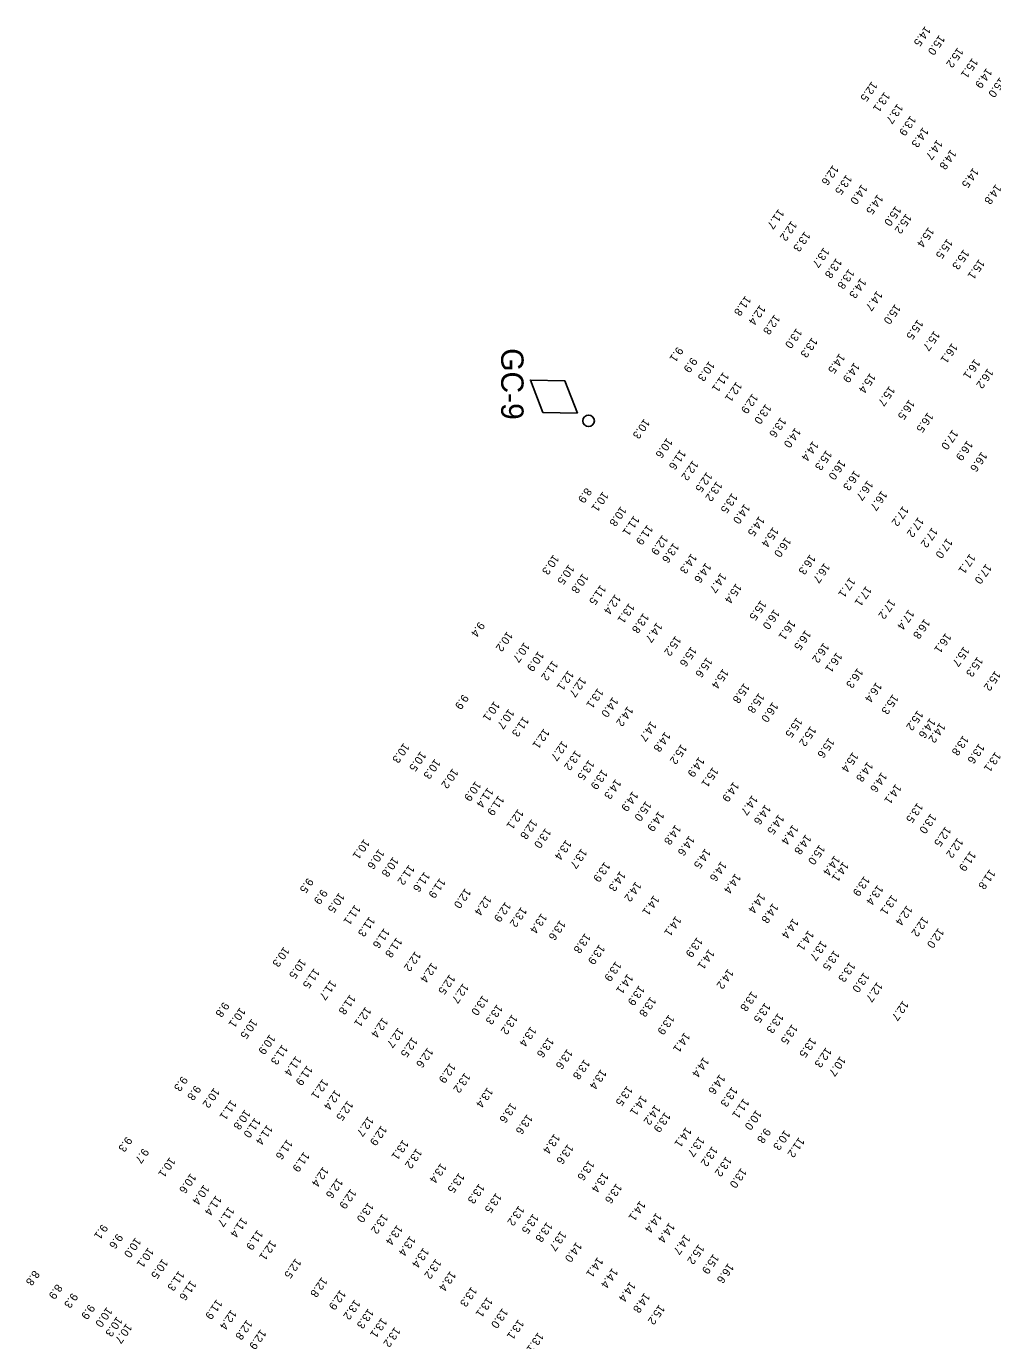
# Model space of a CAD drawing. Extents: x 815385 to 820851, y 582449 to 604245.
# Drawn here: x 817976 to 818580, y 586286 to 587107 of the extents above; entities that cross this region are included whole.
import ezdxf

# ---------------------------------------------------------------- set-up
doc = ezdxf.new("R2010")
doc.units = 0
doc.layers.add('V-CHAN-AIDS', color=7, linetype='Continuous')
doc.layers.add('V-TOPO-SOUN-021509', color=7, linetype='Continuous')

msp = doc.modelspace()

# ---------------------------------------------------------------- linework, layer by layer
at = {"layer": 'V-CHAN-AIDS'}
msp.add_lwpolyline([(818320.2, 586865.49), (818312.34, 586885.64), (818290.71, 586886.14), (818298.57, 586865.98)], close=True, dxfattribs=at)
msp.add_circle((818327.08, 586860.67), 3.6, dxfattribs=at)

# ---------------------------------------------------------------- texts
msp.add_text('GC-9', height=14, rotation=270, dxfattribs=at).set_placement((818272.45, 586906.09))
at = {"layer": 'V-TOPO-SOUN-021509'}
for s, p in [('14.5 ', (818537.41, 587107.56)), ('15.0 ', (818546.24, 587102.05)), ('15.2 ', (818557.74, 587094.19)), ('15.1 ', (818566.9, 587087.65)), ('14.9 ', (818575.73, 587081.34)), ('12.5 ', (818504.07, 587073.04)), ('15.0 ', (818584.05, 587075.59)), ('13.1 ', (818511.97, 587066.46)), ('13.7 ', (818520.11, 587059.15)), ('13.9 ', (818528.25, 587051.65)), ('14.3 ', (818536.02, 587044.36)), ('14.7 ', (818544.83, 587036.63)), ('14.8 ', (818553.43, 587030.51)), ('12.6 ', (818479.79, 587020.77)), ('14.5 ', (818567.4, 587019.07)), ('13.5 ', (818488.19, 587014.8)), ('14.0 ', (818497.76, 587008.77)), ('14.5 ', (818507.67, 587002.5)), ('14.8 ', (818581.54, 587008.83)), ('15.0 ', (818518.97, 586995.26)), ('11.7 ', (818445.8, 586993.34)), ('12.2 ', (818453.81, 586985.94)), ('15.2 ', (818525.5, 586990.44)), ('13.3 ', (818462.13, 586979.29)), ('15.4 ', (818539.49, 586981.97)), ('13.7 ', (818474.06, 586969.28)), ('15.5 ', (818551.19, 586974.78)), ('13.8 ', (818481.87, 586962.59)), ('15.3 ', (818561.46, 586968.11)), ('15.1 ', (818571.12, 586962)), ('13.8 ', (818489.7, 586955.88)), ('14.3 ', (818497.12, 586950.13)), ('11.8 ', (818425.1, 586939.15)), ('14.7 ', (818507.27, 586942.24)), ('12.4 ', (818434.17, 586933.43)), ('15.0 ', (818518.63, 586933.92)), ('12.8 ', (818443.29, 586927.41)), ('15.5 ', (818532.72, 586924.32)), ('13.0 ', (818456.99, 586918.82)), ('13.3 ', (818466.67, 586913.05)), ('15.7 ', (818543.09, 586917.26)), ('9.1', (818382.67, 586907.3)), ('16.1 ', (818554.21, 586909.55)), ('9.9', (818391.46, 586900.67)), ('10.3 ', (818402.44, 586898.32)), ('14.5 ', (818483.85, 586903.1)), ('14.9 ', (818493.07, 586897.44)), ('16.1 ', (818568.31, 586899.64)), ('11.1 ', (818411.31, 586891.52)), ('15.4 ', (818503.04, 586890.87)), ('16.2 ', (818576.52, 586893.79)), ('12.1 ', (818419.46, 586885.47)), ('15.7 ', (818515.03, 586882.74)), ('12.9 ', (818429.48, 586878.07)), ('13.0 ', (818437.77, 586871.57)), ('16.5 ', (818527.43, 586874.29)), ('13.6 ', (818447.1, 586863.19)), ('16.5 ', (818539.02, 586866.33)), ('10.3 ', (818361.86, 586862.37)), ('14.0 ', (818456.22, 586856.75)), ('17.0 ', (818554.55, 586855.55)), ('10.6 ', (818376.08, 586850.31)), ('14.4 ', (818467.25, 586848.42)), ('16.9 ', (818563.71, 586848.72)), ('11.6 ', (818384.4, 586843.04)), ('15.3 ', (818475.67, 586842.69)), ('16.6 ', (818572.69, 586841.75)), ('12.2 ', (818392.2, 586836.33)), ('16.0 ', (818484.17, 586836.73)), ('16.3 ', (818493.24, 586830.07)), ('12.5 ', (818400.9, 586829.01)), ('13.2 ', (818407.15, 586823.27)), ('16.7 ', (818501.42, 586823.83)), ('8.9', (818325.49, 586819.23)), ('10.1 ', (818336.01, 586816.82)), ('13.5 ', (818416.71, 586815.85)), ('16.7 ', (818510.19, 586817.44)), ('10.8 ', (818347.26, 586807.64)), ('14.0 ', (818424.51, 586809.2)), ('17.2 ', (818523.55, 586807.79)), ('11.1 ', (818355.45, 586801.81)), ('14.5 ', (818433.65, 586801.47)), ('17.2 ', (818533.07, 586800.85)), ('11.9 ', (818363.81, 586796.07)), ('12.9 ', (818373.25, 586789.75)), ('15.4 ', (818442.33, 586794.65)), ('17.2 ', (818541.78, 586794.41)), ('13.6 ', (818380.13, 586784.84)), ('16.0 ', (818450.15, 586788.39)), ('17.0 ', (818551.03, 586787.66)), ('10.3 ', (818305.13, 586777.46)), ('14.3 ', (818391.25, 586778.14)), ('14.6 ', (818400.25, 586772.34)), ('16.3 ', (818465.44, 586777.55)), ('16.7 ', (818474.43, 586772.27)), ('17.1 ', (818565.35, 586778.03)), ('10.5 ', (818314.67, 586771.28)), ('10.8 ', (818323.42, 586765.79)), ('14.7 ', (818409.74, 586766.09)), ('17.0 ', (818575.46, 586771.7)), ('11.5 ', (818334.55, 586758.61)), ('15.4 ', (818419.27, 586759.52)), ('17.1 ', (818490.29, 586763.2)), ('17.1 ', (818500.51, 586757.82)), ('12.4 ', (818343.74, 586752.69)), ('15.5 ', (818434.68, 586748.93)), ('17.2 ', (818515.26, 586749.74)), ('13.1 ', (818352.35, 586747.12)), ('13.8 ', (818361.31, 586740.93)), ('16.0 ', (818443.03, 586743.31)), ('17.4 ', (818527.09, 586743.07)), ('9.4', (818258.64, 586735.54)), ('14.7 ', (818369.7, 586735.12)), ('16.1 ', (818452.92, 586736.67)), ('16.8 ', (818536.99, 586737.37)), ('10.2 ', (818276.24, 586729.48)), ('15.2 ', (818381.43, 586726.69)), ('16.5 ', (818462.57, 586730.29)), ('16.1 ', (818550.24, 586728.53)), ('10.7 ', (818286.85, 586722.66)), ('10.9 ', (818295.67, 586717.07)), ('15.6 ', (818391.18, 586720)), ('16.2 ', (818473.93, 586722.41)), ('16.1 ', (818482.11, 586716.43)), ('15.7 ', (818561.55, 586720.07)), ('11.2 ', (818304.56, 586711.27)), ('15.6 ', (818400.95, 586713.26)), ('16.3 ', (818495.17, 586706.62)), ('15.3 ', (818570.1, 586713.68)), ('12.1 ', (818314.37, 586705.13)), ('12.7 ', (818322.09, 586701.01)), ('15.4 ', (818411.11, 586706.23)), ('15.2 ', (818581.16, 586704.93)), ('13.1 ', (818332.83, 586694.03)), ('15.8 ', (818424.26, 586697.2)), ('15.8 ', (818433.5, 586691.02)), ('16.4 ', (818506.87, 586697.72)), ('15.3 ', (818517.2, 586690.25)), ('9.9', (818248.56, 586690.26)), ('10.1 ', (818268.13, 586685.89)), ('14.0 ', (818342.14, 586688.44)), ('14.2 ', (818351.48, 586682.73)), ('16.0 ', (818442.11, 586685.32)), ('10.7 ', (818277.14, 586681.11)), ('11.3 ', (818286.29, 586676.24)), ('15.5 ', (818457.17, 586675.7)), ('15.2 ', (818532.7, 586680.15)), ('14.6 ', (818540.48, 586675.35)), ('12.1 ', (818299.18, 586668.82)), ('14.7 ', (818366.03, 586673.35)), ('14.8 ', (818374.83, 586666.76)), ('15.2 ', (818465.83, 586670.29)), ('14.2 ', (818546.61, 586672.44)), ('10.3 ', (818211.59, 586659.83)), ('12.7 ', (818310.6, 586661.15)), ('15.2 ', (818385, 586659.08)), ('15.6 ', (818477.22, 586662.96)), ('13.8 ', (818561.16, 586664.51)), ('13.6 ', (818571.04, 586659.43)), ('10.5 ', (818222.1, 586654.6)), ('10.3 ', (818231.04, 586649.86)), ('13.2 ', (818318.89, 586655.2)), ('13.5 ', (818327.23, 586649.16)), ('14.9 ', (818396.06, 586651.07)), ('15.4 ', (818492.18, 586654.08)), ('13.1 ', (818581.29, 586654.25)), ('10.2 ', (818242.16, 586643.93)), ('13.9 ', (818335.51, 586643.29)), ('15.1 ', (818404.73, 586644.72)), ('14.8 ', (818501.41, 586648.1)), ('14.6 ', (818510.15, 586641.5)), ('10.9 ', (818256.44, 586635.98)), ('14.3 ', (818343.97, 586637.28)), ('14.9 ', (818417.65, 586635.59)), ('14.1 ', (818519.02, 586634.23)), ('11.4 ', (818264.1, 586631.95)), ('11.9 ', (818270.84, 586627.01)), ('14.9 ', (818354.6, 586629.63)), ('14.7 ', (818429.34, 586627.21)), ('12.1 ', (818282.97, 586618.48)), ('15.0 ', (818362.89, 586623.52)), ('14.9 ', (818370.88, 586617.14)), ('14.6 ', (818437.48, 586621.34)), ('13.5 ', (818532.59, 586622.48)), ('12.8 ', (818291.54, 586612.2)), ('14.8 ', (818381.35, 586608.75)), ('14.5 ', (818445.83, 586615.22)), ('14.4 ', (818454.65, 586608.79)), ('13.0 ', (818540.94, 586615.74)), ('10.1 ', (818186.81, 586599.76)), ('13.0 ', (818300.16, 586606.6)), ('14.6 ', (818389.95, 586601.9)), ('14.8 ', (818462.76, 586602.68)), ('12.5 ', (818550.14, 586607.68)), ('12.2 ', (818557.67, 586600.56)), ('10.6 ', (818195.98, 586593.51)), ('13.4 ', (818312.96, 586599.28)), ('13.7 ', (818322.66, 586593.89)), ('14.5 ', (818399.96, 586593.89)), ('15.0 ', (818471.39, 586596.29)), ('11.9 ', (818565.63, 586592.24)), ('10.8 ', (818204.9, 586588.66)), ('11.2 ', (818214.83, 586583.68)), ('13.9 ', (818337.09, 586585.52)), ('14.6 ', (818409.93, 586585.88)), ('14.4 ', (818480.77, 586589.5)), ('14.1 ', (818486.17, 586585.68)), ('9.5', (818151.57, 586575.55)), ('11.6 ', (818224.51, 586579.33)), ('11.9 ', (818234.17, 586575.4)), ('14.3 ', (818346.78, 586579.73)), ('14.4 ', (818418.77, 586578.27)), ('13.9 ', (818499.34, 586576.69)), ('11.8 ', (818577.77, 586580.89)), ('9.9', (818160.36, 586568.53)), ('12.0 ', (818250.04, 586569.04)), ('14.2 ', (818356.55, 586573.24)), ('13.4 ', (818507.72, 586571.11)), ('10.5 ', (818171.2, 586566.28)), ('11.1 ', (818181.07, 586558.71)), ('12.4 ', (818262.89, 586564.57)), ('12.9 ', (818275.09, 586560.54)), ('14.1 ', (818367.82, 586564.66)), ('14.4 ', (818434.01, 586566)), ('14.8 ', (818442.2, 586559.76)), ('13.1 ', (818516.52, 586564.96)), ('11.3 ', (818190.11, 586551.36)), ('13.2 ', (818285.03, 586557.34)), ('13.4 ', (818297.62, 586553.41)), ('14.1 ', (818381.53, 586551.7)), ('12.4 ', (818525.98, 586558.35)), ('12.2 ', (818535.93, 586551.38)), ('11.6 ', (818199.34, 586544.11)), ('13.6 ', (818309.24, 586549.11)), ('14.4 ', (818454.81, 586550.18)), ('14.1 ', (818464.4, 586542.69)), ('12.0 ', (818545.66, 586544.2)), ('11.8 ', (818207.11, 586538.3)), ('13.8 ', (818324.87, 586540.95)), ('13.9 ', (818394.89, 586538.47)), ('13.7 ', (818472.48, 586536.37)), ('10.3 ', (818136.67, 586532.47)), ('12.2 ', (818218.79, 586529.69)), ('13.9 ', (818333.81, 586533.94)), ('14.1 ', (818402.27, 586530.94)), ('13.5 ', (818480.48, 586530.27)), ('10.5 ', (818147.05, 586525.06)), ('11.5 ', (818155.58, 586519.07)), ('12.4 ', (818229.03, 586522.63)), ('13.9 ', (818344.07, 586523.46)), ('14.2 ', (818414.21, 586518.7)), ('13.3 ', (818490.25, 586523.01)), ('11.7 ', (818165.94, 586511.77)), ('12.5 ', (818240.26, 586515.25)), ('12.7 ', (818248.67, 586509.73)), ('14.1 ', (818351.45, 586515.61)), ('13.0 ', (818499.05, 586516.5)), ('12.7 ', (818507.44, 586510.5)), ('11.8 ', (818178.02, 586502.68)), ('13.0 ', (818260.92, 586502.2)), ('13.9 ', (818358.68, 586508.35)), ('13.8 ', (818365.82, 586501.28)), ('13.8 ', (818429.01, 586504.72)), ('9.8', (818098.96, 586498.03)), ('10.1 ', (818109.24, 586494.55)), ('12.1 ', (818187.74, 586495.01)), ('13.3 ', (818269.88, 586496.51)), ('13.5 ', (818437.32, 586497.55)), ('12.7 ', (818523.56, 586498.88)), ('10.5 ', (818116.59, 586487.5)), ('12.4 ', (818198.33, 586488.26)), ('13.2 ', (818279.32, 586490.27)), ('13.9 ', (818377.25, 586490.1)), ('13.3 ', (818445.43, 586491.01)), ('10.9 ', (818127.84, 586477.79)), ('12.7 ', (818208.05, 586481.99)), ('13.4 ', (818290.96, 586482.68)), ('14.1 ', (818387.04, 586479.02)), ('13.5 ', (818454.27, 586484.15)), ('11.3 ', (818135.65, 586471.37)), ('12.5 ', (818216.78, 586476.02)), ('12.6 ', (818226.48, 586469.5)), ('13.6 ', (818301.88, 586475.87)), ('13.6 ', (818313.71, 586468.62)), ('13.5 ', (818465.85, 586475.83)), ('12.3 ', (818475.44, 586469.64)), ('11.4 ', (818144.15, 586464.27)), ('13.8 ', (818324.42, 586462.17)), ('14.4 ', (818398.92, 586463.52)), ('10.7 ', (818484.32, 586464.11)), ('11.9 ', (818151.15, 586458.4)), ('12.9 ', (818240.57, 586459.89)), ('13.2 ', (818249.7, 586453.82)), ('13.4 ', (818334.82, 586456)), ('14.6 ', (818409, 586452.86)), ('9.3', (818073.01, 586451.73)), ('9.8', (818081.29, 586446.04)), ('10.2 ', (818093.03, 586444.39)), ('12.1 ', (818160.9, 586449.95)), ('13.4 ', (818263.86, 586444.59)), ('13.5 ', (818351.13, 586445.65)), ('13.3 ', (818416.69, 586445.06)), ('11.1 ', (818103.63, 586436.88)), ('12.4 ', (818168.72, 586443.16)), ('12.5 ', (818176.5, 586436.38)), ('14.1 ', (818360.04, 586439.64)), ('11.1 ', (818423.96, 586437.77)), ('10.8 ', (818112.31, 586430.78)), ('13.6 ', (818278.52, 586435.06)), ('13.6 ', (818288.68, 586427.88)), ('14.2 ', (818368.63, 586433.79)), ('13.9 ', (818374.82, 586429.15)), ('10.0 ', (818431.81, 586430.58)), ('11.0 ', (818118.59, 586425.75)), ('11.4 ', (818126.23, 586421.3)), ('12.7 ', (818189.28, 586426.54)), ('12.9 ', (818197.57, 586420.84)), ('14.1 ', (818387.93, 586419.84)), ('9.3', (818038.3, 586413.93)), ('11.6 ', (818138.68, 586412.17)), ('13.1 ', (818211.08, 586411.96)), ('13.4 ', (818305.69, 586415.74)), ('13.7 ', (818396.02, 586413.9)), ('9.8', (818437.39, 586419.32)), ('10.3 ', (818449.58, 586417.99)), ('11.2 ', (818458.55, 586413.46)), ('9.7', (818048.73, 586406.73)), ('11.9 ', (818149.2, 586404.41)), ('13.2 ', (818219.51, 586406.5)), ('13.6 ', (818314.13, 586409.27)), ('13.2 ', (818404.33, 586407.84)), ('10.1 ', (818065.37, 586401.01)), ('12.4 ', (818161.2, 586395.12)), ('13.4 ', (818234.79, 586397.39)), ('13.6 ', (818327.24, 586399.08)), ('13.2 ', (818413.04, 586401.51)), ('10.6 ', (818078.39, 586390.99)), ('12.6 ', (818170.06, 586387.95)), ('13.5 ', (818246.08, 586391.26)), ('13.4 ', (818336.05, 586391.53)), ('13.0 ', (818422.42, 586394.32)), ('10.4 ', (818086.66, 586383.92)), ('12.9 ', (818178.44, 586381.32)), ('13.3 ', (818258.67, 586384.58)), ('13.5 ', (818269.26, 586378.77)), ('13.6 ', (818344.45, 586384.69)), ('11.4 ', (818094.26, 586377.2)), ('11.7 ', (818102.21, 586370.18)), ('13.0 ', (818189.35, 586372.82)), ('13.2 ', (818283.46, 586370.78)), ('14.1 ', (818359.19, 586373.81)), ('11.4 ', (818110.31, 586363.46)), ('13.2 ', (818198.26, 586365.75)), ('13.5 ', (818292.37, 586365.76)), ('14.4 ', (818369.36, 586366.38)), ('9.1', (818023.1, 586359.28)), ('11.9 ', (818120.21, 586355.62)), ('13.4 ', (818207.42, 586358.75)), ('13.8 ', (818301.03, 586360.57)), ('13.7 ', (818309.68, 586355.02)), ('14.4 ', (818377.49, 586360.18)), ('9.6', (818032.51, 586353.37)), ('10.0 ', (818043.93, 586350.86)), ('12.1 ', (818128.4, 586349.22)), ('13.4 ', (818215.5, 586351.9)), ('14.0 ', (818319.41, 586348.04)), ('14.7 ', (818387.18, 586352.78)), ('15.2 ', (818395.9, 586346.7)), ('10.1 ', (818051.87, 586344.61)), ('10.5 ', (818060.79, 586337.63)), ('12.5 ', (818144.03, 586337.88)), ('13.4 ', (818223.88, 586344.55)), ('13.2 ', (818231.59, 586337.61)), ('14.1 ', (818332.73, 586338.57)), ('15.9 ', (818405.07, 586340.66)), ('8.8', (817980.47, 586330.43)), ('11.3 ', (818071.07, 586330.13)), ('13.4 ', (818240.67, 586329.95)), ('14.4 ', (818341.92, 586331.84)), ('16.6 ', (818414.35, 586334.85)), ('8.9', (817994.72, 586321.86)), ('11.6 ', (818078.46, 586324.14)), ('12.8 ', (818160.35, 586326.12)), ('14.4 ', (818353.04, 586323.28)), ('9.3', (818004.37, 586316.33)), ('12.9 ', (818171.9, 586318.21)), ('13.3 ', (818253.89, 586320.17)), ('13.1 ', (818263.71, 586313.61)), ('14.8 ', (818362, 586316.38)), ('9.9', (818015.05, 586309.25)), ('10.0 ', (818026.01, 586307.41)), ('11.9 ', (818094.71, 586312.3)), ('12.4 ', (818103.74, 586305.85)), ('13.2 ', (818180.92, 586312.1)), ('13.3 ', (818189.37, 586306.52)), ('13.0 ', (818273.26, 586306.77)), ('15.2 ', (818371.24, 586309.01)), ('10.3 ', (818032.3, 586301.52)), ('10.7 ', (818038.29, 586297.24)), ('12.8 ', (818113.5, 586299.51)), ('13.1 ', (818197.72, 586300.76)), ('13.1 ', (818283.2, 586299.7)), ('12.9 ', (818122.14, 586293.54)), ('13.2 ', (818205.99, 586294.98)), ('13.1 ', (818295.51, 586291.66))]:
    msp.add_text(s, height=5, rotation=234.911, dxfattribs=at).set_placement(p)

doc.saveas('drawing.dxf')
